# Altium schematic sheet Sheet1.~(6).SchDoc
size A2; SheetNumber: 1; SheetTotal: 1
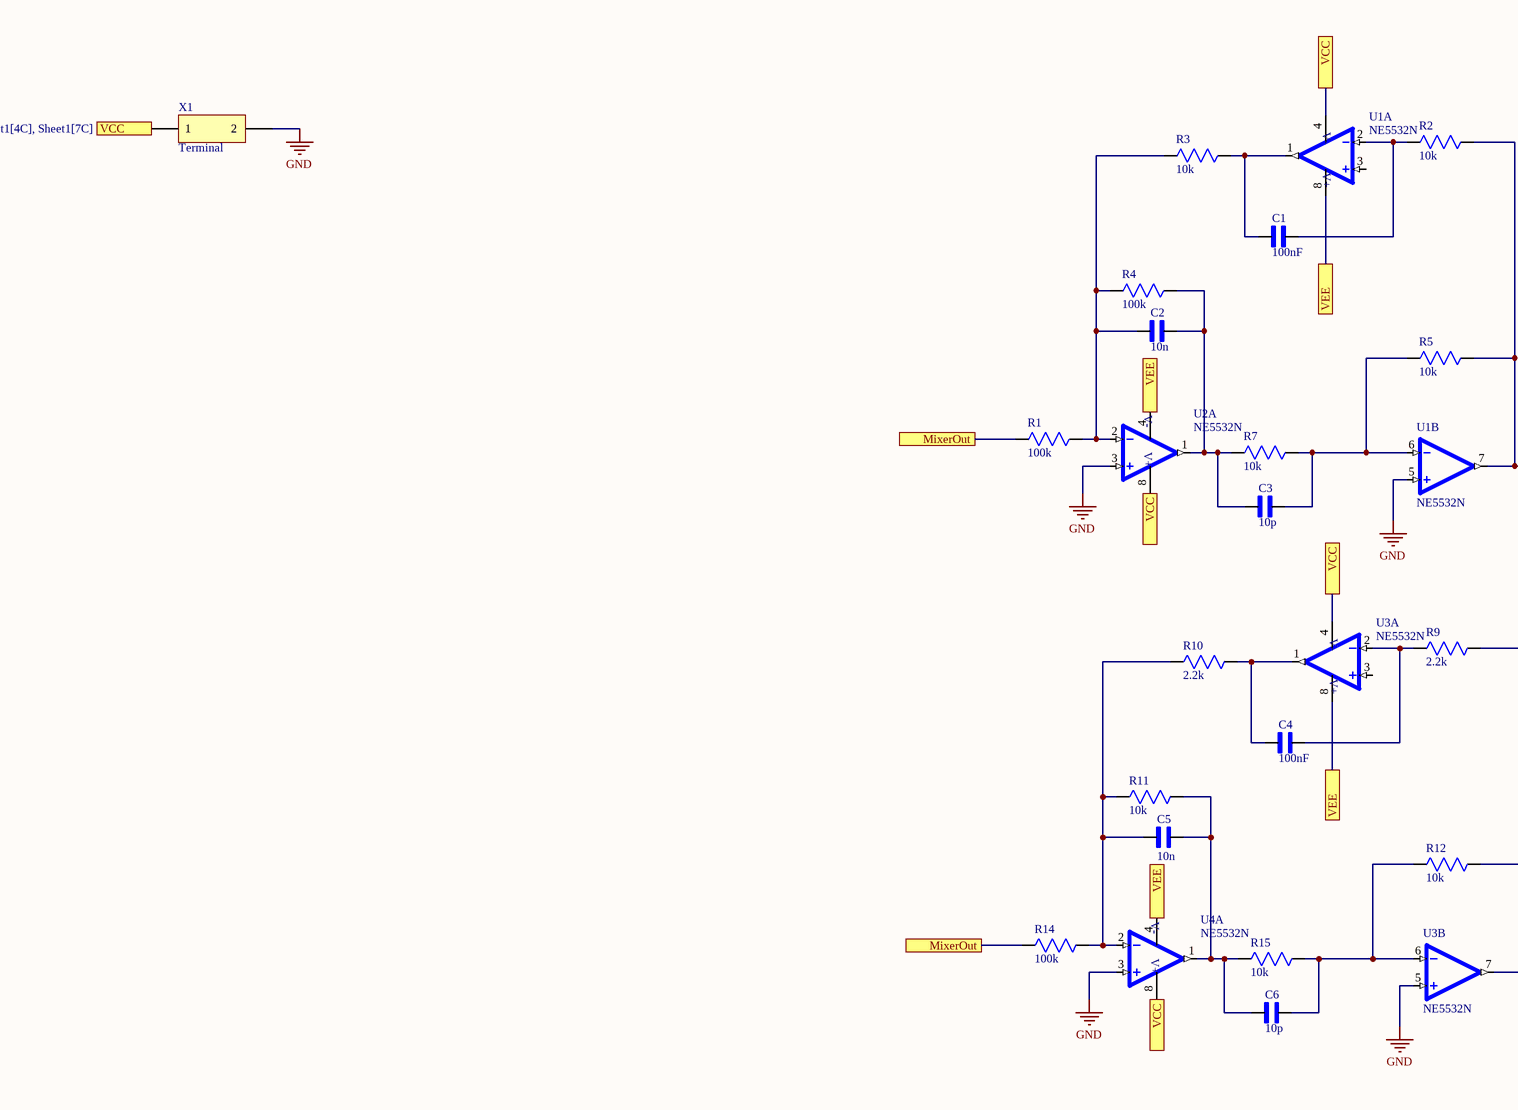
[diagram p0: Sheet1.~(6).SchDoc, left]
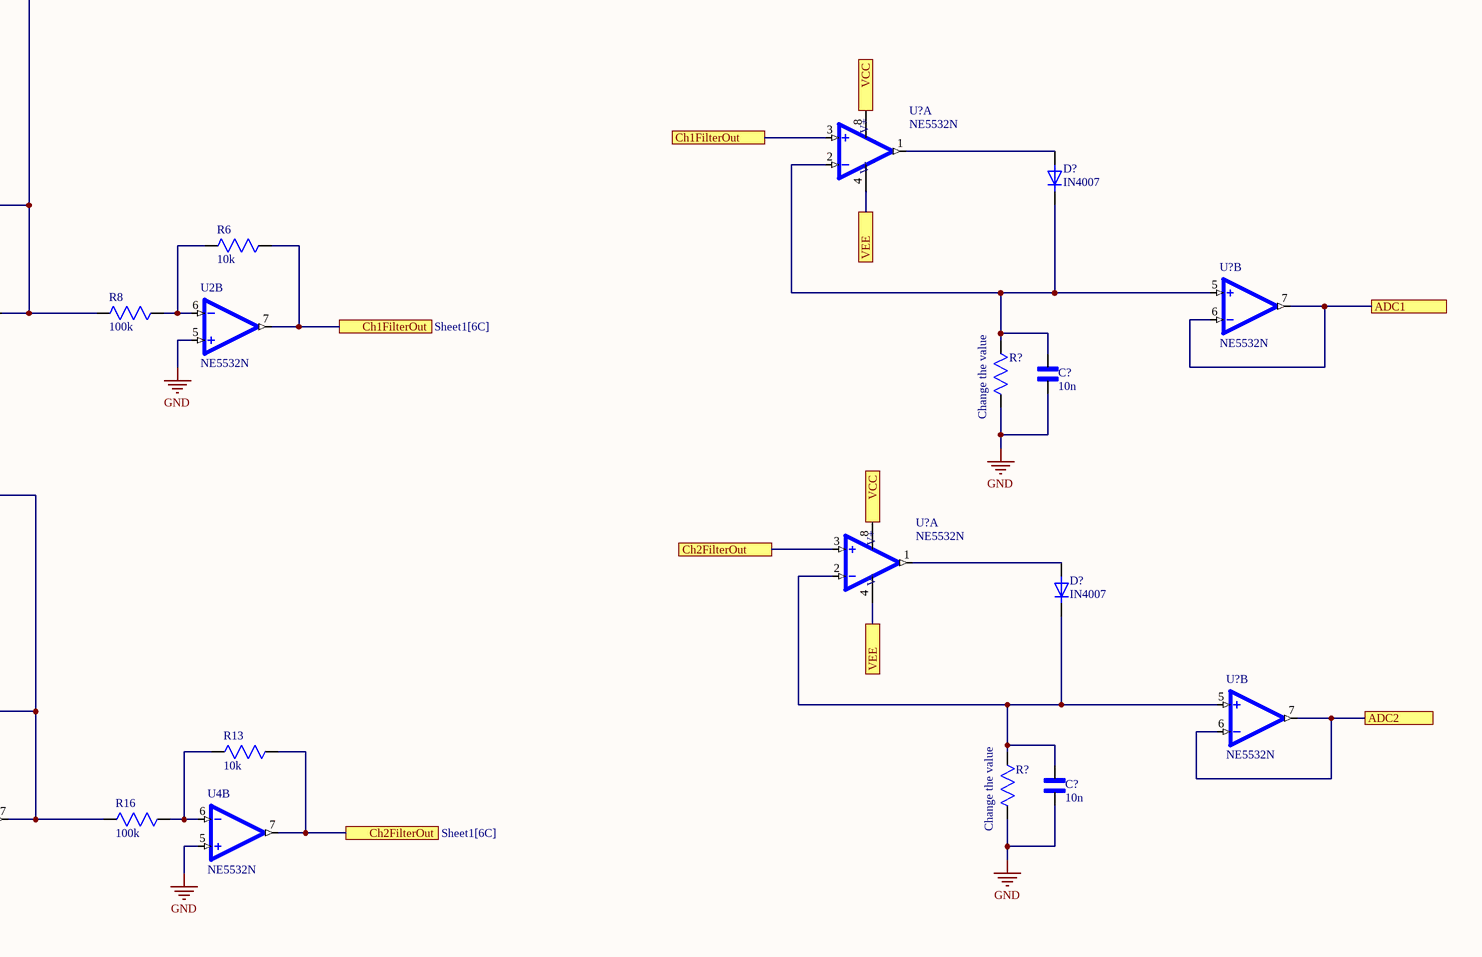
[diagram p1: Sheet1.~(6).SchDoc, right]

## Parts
(Parts that share a designator on the sheet are numbered #1, #2 ... from top to bottom, then left to right.)
C1  100nF  [CAPC2012X95N]
C2  10n  [CAPC2012X95N]
C3  10p  [CAPC2012X95N]
C4  100nF  [CAPC2012X95N]
C5  10n  [CAPC2012X95N]
C6  10p  [CAPC2012X95N]
C?#1  10n  [CAPC2012X95N]
C?#2  10n  [CAPC2012X95N]
D?#1  IN4007  [DIOAD1070W78L470D235P]
D?#2  IN4007  [DIOAD1070W78L470D235P]
R1  100k  [RC0805N_YAG-M]
R2  10k  [RC0805N_YAG-M]
R3  10k  [RC0805N_YAG-M]
R4  100k  [RC0805N_YAG-M]
R5  10k  [RC0805N_YAG-M]
R6  10k  [RC0805N_YAG-M]
R7  10k  [RC0805N_YAG-M]
R8  100k  [RC0805N_YAG-M]
R9  2.2k  [RC0805N_YAG-M]
R10  2.2k  [RC0805N_YAG-M]
R11  10k  [RC0805N_YAG-M]
R12  10k  [RC0805N_YAG-M]
R13  10k  [RC0805N_YAG-M]
R14  100k  [RC0805N_YAG-M]
R15  10k  [RC0805N_YAG-M]
R16  100k  [RC0805N_YAG-M]
R?#1  Change the value  [RC0805N_YAG-M]
R?#2  Change the value  [RC0805N_YAG-M]
U1  NE5532N  [DIP766W45P254L1016H533Q8]  (parts A,B of 2)
U2  NE5532N  [DIP766W45P254L1016H533Q8]  (parts A,B of 2)
U3  NE5532N  [DIP766W45P254L1016H533Q8]  (parts A,B of 2)
U4  NE5532N  [DIP766W45P254L1016H533Q8]  (parts A,B of 2)
U?#1  NE5532N  [DIP766W45P254L1016H533Q8]  (part A of 2)
U?#2  NE5532N  [DIP766W45P254L1016H533Q8]  (part B of 2)
U?#3  NE5532N  [DIP766W45P254L1016H533Q8]  (part A of 2)
U?#4  NE5532N  [DIP766W45P254L1016H533Q8]  (part B of 2)
X1  Terminal  [CON_TERMINAL_2POL]

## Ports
ADC1, ADC2, Ch1FilterOut (see Sheet1[5C]), Ch1FilterOut (see Sheet1[6C]), Ch2FilterOut (see Sheet1[5D]), Ch2FilterOut (see Sheet1[6C]), MixerOut (see Sheet1[3C]), MixerOut (see Sheet1[3D]), VCC (see Sheet1[1B], Sheet1[3C], Sheet1[3D], Sheet1[4B], Sheet1[4C], Sheet1[7C]), VCC (see Sheet1[1B], Sheet1[3C], Sheet1[3D], Sheet1[4B], Sheet1[7C]), VCC (see Sheet1[1B], Sheet1[3C], Sheet1[3D], Sheet1[4C], Sheet1[7C]), VCC (see Sheet1[1B], Sheet1[3C], Sheet1[4B], Sheet1[4C], Sheet1[7C]), VCC (see Sheet1[1B], Sheet1[3D], Sheet1[4B], Sheet1[4C], Sheet1[7C]), VCC (see Sheet1[3C], Sheet1[3D], Sheet1[4B], Sheet1[4C], Sheet1[7C]), VEE (see Sheet1[3C], Sheet1[3D], Sheet1[4C], Sheet1[4D], Sheet1[7C]), VEE (see Sheet1[3C], Sheet1[3D], Sheet1[4C], Sheet1[4D], Sheet1[7D]), VEE (see Sheet1[3C], Sheet1[3D], Sheet1[4C], Sheet1[7C], Sheet1[7D]), VEE (see Sheet1[3C], Sheet1[3D], Sheet1[4D], Sheet1[7C], Sheet1[7D]), VEE (see Sheet1[3C], Sheet1[4C], Sheet1[4D], Sheet1[7C], Sheet1[7D]), VEE (see Sheet1[3D], Sheet1[4C], Sheet1[4D], Sheet1[7C], Sheet1[7D])

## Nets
GND: C?#1.2 C?#2.2 R?#1.1 R?#2.1 U1.5(+INB) U2.3(+INA) U2.5(+INB) U3.5(+INB) U4.3(+INA) U4.5(+INB) X1.2
ADC1: U?#2.6(-INB) U?#2.7(OUTB) ; port ADC1
ADC2: U?#4.6(-INB) U?#4.7(OUTB) ; port ADC2
Ch1FilterOut: R6.1 U2.7(OUTB) U?#1.3(+INA) ; port Ch1FilterOut
Ch2FilterOut: R13.1 U4.7(OUTB) U?#3.3(+INA) ; port Ch2FilterOut
MixerOut: R1.2 R14.2 ; port MixerOut
VCC: U1.4(V-) U2.8(V+) U3.4(V-) U4.8(V+) U?#1.8(V+) U?#3.8(V+) X1.1 ; port VCC
VEE: U1.8(V+) U2.4(V-) U3.8(V+) U4.4(V-) U?#1.4(V-) U?#3.4(V-) ; port VEE
NetC1_1: C1.1 R3.1 U1.1(OUTA)
NetC1_2: C1.2 R2.2 U1.2(-INA)
NetC2_1: C2.1 R1.1 R3.2 R4.2 U2.2(-INA)
NetC2_2: C2.2 C3.1 R4.1 R7.2 U2.1(OUTA)
NetC3_2: C3.2 R5.2 R7.1 U1.6(-INB)
NetC4_1: C4.1 R10.1 U3.1(OUTA)
NetC4_2: C4.2 R9.2 U3.2(-INA)
NetC5_1: C5.1 R10.2 R11.2 R14.1 U4.2(-INA)
NetC5_2: C5.2 C6.1 R11.1 R15.2 U4.1(OUTA)
NetC6_2: C6.2 R12.2 R15.1 U3.6(-INB)
NetC?#1_1: C?#1.1 D?#1.C R?#1.2 U?#1.2(-INA) U?#2.5(+INB)
NetC?#2_1: C?#2.1 D?#2.C R?#2.2 U?#3.2(-INA) U?#4.5(+INB)
NetD?#1_A: D?#1.A U?#1.1(OUTA)
NetD?#2_A: D?#2.A U?#3.1(OUTA)
NetR2_1: R2.1 R5.1 R8.2 U1.7(OUTB)
NetR6_2: R6.2 R8.1 U2.6(-INB)
NetR9_1: R9.1 R12.1 R16.2 U3.7(OUTB)
NetR13_2: R13.2 R16.1 U4.6(-INB)

Not connected (* = marked no-connect by the designer): U1 3(+INA); U3 3(+INA)

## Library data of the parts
C1 C4 = CAP_0805_GENERIC: 0.1 ÂµF Â±10% 50V Ceramic Capacitor X7R 0805 (2012 Metric); MF: Samsung Electro-Mechanics; MP: CL21B104KBCNNNC
C2 C3 C5 C6 C?#1 C?#2 = CAP_0805_GENERIC: 0.1 ÂµF Â±10% 50V Ceramic Capacitor X7R 0805 (2012 Metric); Value: 100nF; MF: Samsung Electro-Mechanics; MP: CL21B104KBCNNNC
D?#1 D?#2 = IN4007: Diode Standard 1000 V 1A Through Hole DO-204AL (DO-41); MF: Vishay Semiconductor
R1 R4 R8-R10 R14 R16 R?#1 R?#2 = RES_0805_GENERIC_1: Description; Manufacturer_Name: Yageo; Manufacturer_Part_Number: RC0805FR-0710KL; Value: 10k
R2 R3 R5-R7 R11-R13 R15 = RES_0805_GENERIC_1: Description; Manufacturer_Name: Yageo; Manufacturer_Part_Number: RC0805FR-0710KL
U1-U4 U?#1-U?#4 = NE5532N: IC, OP AMP, DUAL; No. of Amplifiers: 2 Amplifier; Bandwidth: 10MHz; Slew Rate: 8V/Âµs; Supply Voltage Range: Â± 15V; Amplifier Case Style: DIP; No. of Pins: 8Pins; Operating Temperature Min: 0Â°C; Operating Temperature Max: 70Â°C; MSL: -; SVHC: No SVHC (1; MF: Fairchild Semiconductor
X1 = CON_TERMINAL_2POL: Terminal Screw; Manufacturer_Name: Yageo; Manufacturer_Part_Number: RC0805FR-0710KL; Value: 10k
